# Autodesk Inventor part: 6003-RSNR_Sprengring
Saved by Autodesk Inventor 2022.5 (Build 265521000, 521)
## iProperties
Created: 2024-12
Part Number: 6003-RSNR_Sprengring
Material: Generic
Document SubType Name: Modeling
Designer: AdminForWorker
Density: 1 g/cm^3
Appearance: Default
Title: 6003-RSNR_Sprengring
Author: AdminForWorker
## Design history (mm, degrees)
feature "Body1"
body "Solid1"
